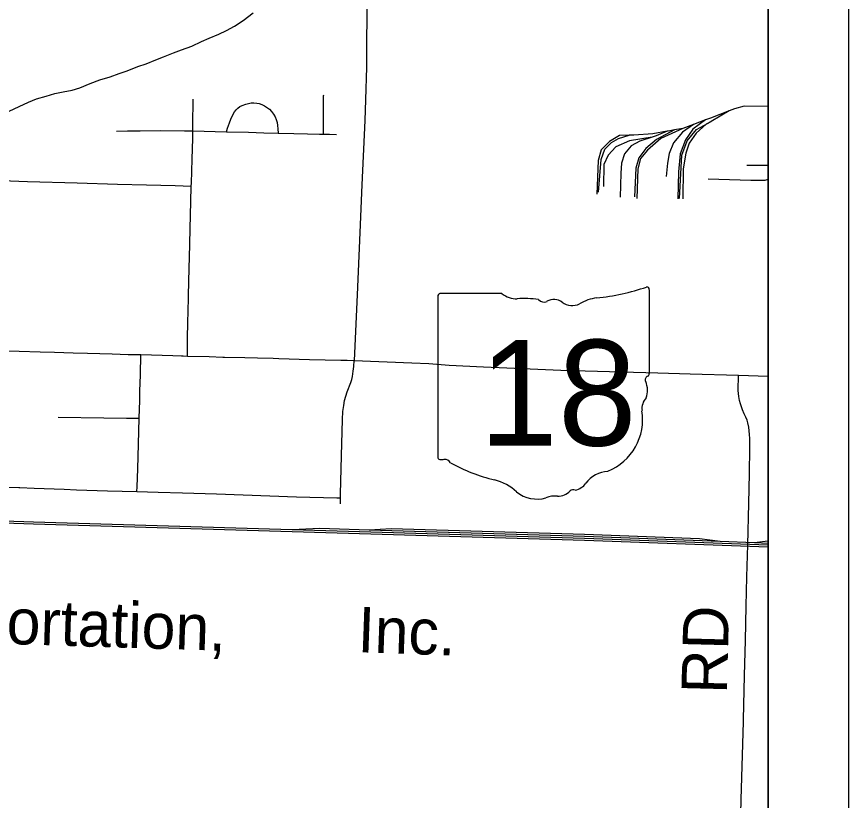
# Model space of a CAD drawing. Extents: x 0 to 34, y 0 to 22.
# Drawn here: x 29.379 to 30.417, y 17.811 to 18.788 of the extents above; entities that cross this region are included whole.
import ezdxf

# ---------------------------------------------------------------- set-up
doc = ezdxf.new("R2010")
doc.units = 0
for name, color, linetype in [('GM_X_City_Street', 7, 'Continuous'), ('GM_X_County_Road', 7, 'Continuous'), ('GM_X_County_Road_Text', 7, 'Continuous'), ('GM_X_Major_River', 7, 'Continuous'), ('GM_X_Rail_Line', 7, 'Continuous'), ('GM_X_Rail_Line_Text', 7, 'Continuous'), ('GM_X_State_Location', 7, 'Continuous'), ('GM_X_State_Route', 7, 'Continuous'), ('GM_X_State_Shield', 7, 'Continuous'), ('GM_X_Township_Road', 7, 'Continuous'), ('SH_Data', 7, 'Continuous')]:
    doc.layers.add(name, color=color, linetype=linetype)

msp = doc.modelspace()

# ---------------------------------------------------------------- linework, layer by layer
at = {"layer": 'GM_X_City_Street'}
msp.add_line((29.599, 18.6457), (29.6412, 18.6447), dxfattribs=at)
for points in [[(29.762, 18.6418), (29.762, 18.6529), (29.7621, 18.6674), (29.7622, 18.6797), (29.7623, 18.6895), (29.7624, 18.6908)], [(29.6412, 18.6447), (29.6426, 18.6492), (29.6438, 18.6527), (29.6449, 18.6557), (29.6465, 18.6603), (29.6494, 18.6665), (29.6512, 18.6697), (29.6532, 18.6722), (29.6555, 18.6742), (29.658, 18.676), (29.6608, 18.6774), (29.6654, 18.6792), (29.6684, 18.6801), (29.6721, 18.6807), (29.6751, 18.6808), (29.6789, 18.6805), (29.6819, 18.6799), (29.6854, 18.6786), (29.6887, 18.677), (29.6924, 18.6747), (29.6948, 18.6727), (29.6974, 18.67), (29.6999, 18.6665), (29.7018, 18.6633), (29.7033, 18.6599), (29.7043, 18.6563), (29.7049, 18.6526), (29.7051, 18.6483), (29.7054, 18.643)], [(29.5039, 18.6455), (29.5176, 18.6458), (29.5337, 18.646), (29.5591, 18.6462), (29.5887, 18.6459), (29.599, 18.6457)], [(29.6412, 18.6447), (29.6686, 18.6441), (29.6879, 18.6434), (29.7054, 18.643)], [(29.7054, 18.643), (29.7253, 18.6425), (29.7421, 18.6422), (29.757, 18.6419), (29.762, 18.6418)], [(29.762, 18.6418), (29.7696, 18.6416), (29.7782, 18.6414)], [(29.1792, 18.5679), (29.1884, 18.5693), (29.2024, 18.5719), (29.2172, 18.574), (29.2197, 18.5744), (29.2651, 18.5814), (29.2805, 18.5838), (29.2899, 18.5849), (29.2918, 18.5852), (29.3009, 18.5858), (29.3075, 18.5861), (29.3284, 18.5851), (29.393, 18.5828), (29.4549, 18.5811), (29.5053, 18.5794), (29.5415, 18.5786), (29.577, 18.5776), (29.5973, 18.5768)], [(29.4311, 18.2889), (29.4884, 18.2881), (29.5163, 18.2876), (29.5324, 18.2874)]]:
    msp.add_lwpolyline(points, dxfattribs=at)
at = {"layer": 'GM_X_County_Road'}
for points in [[(30.2938, 18.2543), (30.2936, 18.2623), (30.2934, 18.2673), (30.293, 18.2719), (30.2924, 18.2761), (30.2914, 18.2818), (30.2903, 18.2852), (30.2889, 18.2886), (30.2869, 18.2931), (30.2847, 18.298), (30.2834, 18.3015), (30.282, 18.3054), (30.2808, 18.3094), (30.2803, 18.3119), (30.2799, 18.3145), (30.2791, 18.3219), (30.2798, 18.3413)], [(30.2714, 17.3404), (30.2716, 17.3482), (30.2721, 17.3787), (30.273, 17.4172), (30.2745, 17.4707), (30.2772, 17.5689), (30.2807, 17.7224), (30.283, 17.812), (30.2857, 17.9089), (30.2857, 17.9102), (30.2858, 17.9114), (30.287, 17.9667), (30.2885, 18.0102), (30.2894, 18.0531), (30.2902, 18.0898), (30.2911, 18.1296), (30.2925, 18.1812), (30.2935, 18.2184), (30.2939, 18.2503), (30.2938, 18.2543)]]:
    msp.add_lwpolyline(points, dxfattribs=at)
at = {"layer": 'GM_X_Major_River'}
msp.add_lwpolyline([(29.3701, 18.6702), (29.3827, 18.6764), (29.3943, 18.6818), (29.4042, 18.6857), (29.4161, 18.6892), (29.4271, 18.6923), (29.4374, 18.6947), (29.4485, 18.6967), (29.4584, 18.6995), (29.4711, 18.7048), (29.4833, 18.7094), (29.496, 18.7133), (29.5074, 18.7172), (29.5174, 18.7207), (29.5308, 18.7261), (29.5411, 18.7296), (29.553, 18.7342), (29.5626, 18.7381), (29.5749, 18.7431), (29.5852, 18.747), (29.5978, 18.7516), (29.6101, 18.7574), (29.6197, 18.7613), (29.6316, 18.7663), (29.6412, 18.771), (29.6512, 18.7765), (29.662, 18.7834), (29.6744, 18.7929)], dxfattribs=at)
at = {"layer": 'GM_X_Rail_Line'}
for p, q in [((30.2681, 18.6708), (30.2454, 18.6577)), ((30.2383, 18.6594), (30.2235, 18.6539)), ((30.2235, 18.6539), (30.2102, 18.6489)), ((30.2102, 18.6489), (30.2, 18.647)), ((30.2901, 18.6031), (30.3167, 18.6031)), ((30.2569, 18.1341), (30.2995, 18.1325)), ((30.2995, 18.1325), (30.3161, 18.1344)), ((30.2995, 18.1325), (30.3167, 18.1318)), ((30.3161, 18.1344), (30.3167, 18.1343)), ((30.3161, 18.1344), (30.3167, 18.1344))]:
    msp.add_line(p, q, dxfattribs=at)
for points in [[(30.2681, 18.6708), (30.2446, 18.6618), (30.2383, 18.6594)], [(30.3167, 18.6762), (30.2868, 18.6766), (30.2746, 18.6733), (30.2681, 18.6708)], [(30.2383, 18.6594), (30.2227, 18.6481), (30.2135, 18.6348), (30.2069, 18.6172), (30.2048, 18.5947), (30.2038, 18.5611)], [(30.2235, 18.6539), (30.2097, 18.644), (30.1987, 18.6307), (30.1931, 18.6177), (30.1913, 18.6055), (30.1893, 18.5889)], [(30.2061, 18.5615), (30.2092, 18.6157), (30.2158, 18.6335), (30.2271, 18.6475), (30.2454, 18.6577)], [(30.2454, 18.6577), (30.2393, 18.6542), (30.2268, 18.643), (30.2181, 18.6305), (30.2141, 18.6179), (30.2105, 18.5983), (30.2102, 18.5611)], [(30.1433, 18.6403), (30.1314, 18.6399), (30.1188, 18.6327), (30.1083, 18.622), (30.1045, 18.6087), (30.103, 18.5667)], [(30.1051, 18.5692), (30.1084, 18.6101), (30.1129, 18.6228), (30.1214, 18.6315), (30.13, 18.6363), (30.1433, 18.6403)], [(30.1909, 18.6453), (30.173, 18.6422), (30.1492, 18.6405), (30.1433, 18.6403)], [(30.2, 18.647), (30.1776, 18.6351), (30.1643, 18.6238), (30.1553, 18.6123), (30.1518, 18.5994), (30.15, 18.5634)], [(30.2102, 18.6489), (30.1826, 18.6361), (30.166, 18.6218), (30.1576, 18.6113), (30.1543, 18.5985), (30.1528, 18.5615)], [(30.1909, 18.6453), (30.1771, 18.6396), (30.172, 18.6379)], [(30.2, 18.647), (30.1921, 18.6455), (30.1909, 18.6453)], [(30.172, 18.6379), (30.1438, 18.6332), (30.1267, 18.6259), (30.117, 18.6154), (30.1119, 18.6039), (30.1112, 18.5766)], [(30.172, 18.6379), (30.1568, 18.633), (30.1457, 18.6271), (30.1377, 18.617), (30.1337, 18.6054), (30.1329, 18.5929), (30.1319, 18.5633)], [(30.2419, 18.5858), (30.295, 18.5842), (30.3131, 18.5843), (30.3167, 18.5854)], [(28.9595, 18.1734), (29.4006, 18.1583), (30.0875, 18.1379), (30.3167, 18.1294)], [(28.9595, 18.1709), (29.4005, 18.1558), (30.0875, 18.1355), (30.3167, 18.1269)], [(29.7232, 18.1487), (29.7571, 18.1502), (29.8192, 18.1484)], [(29.8192, 18.1484), (29.8464, 18.1501), (30.0877, 18.1429), (30.2312, 18.1375), (30.2569, 18.1341)], [(29.8192, 18.1484), (30.0876, 18.1404), (30.2569, 18.1341)]]:
    msp.add_lwpolyline(points, dxfattribs=at)
at = {"layer": 'GM_X_State_Route'}
for p, q in [((29.6386, 18.3638), (29.6642, 18.3631)), ((29.7915, 18.3597), (29.8003, 18.3595)), ((30.2798, 18.3413), (30.3167, 18.3401))]:
    msp.add_line(p, q, dxfattribs=at)
for points in [[(29.8169, 18.925), (29.8167, 18.9141), (29.8165, 18.8688), (29.8164, 18.8327), (29.8159, 18.7525), (29.8156, 18.7251), (29.8146, 18.6847), (29.8137, 18.6586), (29.8099, 18.5785), (29.8074, 18.519), (29.804, 18.4412), (29.8003, 18.3595)], [(29.0359, 18.3804), (29.0671, 18.3795), (29.0882, 18.3789), (29.115, 18.3783), (29.1473, 18.3774), (29.2326, 18.3751), (29.2717, 18.3742), (29.2836, 18.3739), (29.2862, 18.3739), (29.3144, 18.3728), (29.3528, 18.3717), (29.3672, 18.3713), (29.3825, 18.3709), (29.4088, 18.3702), (29.4267, 18.3697), (29.4498, 18.3691), (29.4679, 18.3685), (29.4986, 18.3677), (29.5187, 18.3671), (29.5212, 18.367), (29.5344, 18.3668)], [(29.5344, 18.3668), (29.5743, 18.3656), (29.5851, 18.3653)], [(29.5851, 18.3653), (29.5871, 18.3652), (29.5925, 18.365)], [(29.5925, 18.365), (29.6197, 18.3643), (29.6366, 18.3638), (29.6386, 18.3638)], [(29.6642, 18.3631), (29.68, 18.3626), (29.6993, 18.3623), (29.7064, 18.3621)], [(29.7064, 18.3621), (29.7447, 18.3608), (29.7836, 18.3599), (29.7915, 18.3597)], [(29.8003, 18.3595), (29.8721, 18.3566), (29.8935, 18.3555), (29.9188, 18.3538), (29.9616, 18.3516), (30.0294, 18.3485), (30.058, 18.3475), (30.0733, 18.3471)], [(30.0733, 18.3471), (30.1792, 18.3439), (30.2195, 18.3428), (30.2798, 18.3413)]]:
    msp.add_lwpolyline(points, dxfattribs=at)
at = {"layer": 'GM_X_State_Shield'}
for p, q in [((29.9846, 18.4428), (29.9074, 18.4428)), ((30.1685, 18.3431), (30.1685, 18.4477)), ((29.9048, 18.4393), (29.9048, 18.2392)), ((30.1684, 18.3431), (30.1685, 18.3431))]:
    msp.add_line(p, q, dxfattribs=at)
for centre, radius, start, end in [((29.9078, 18.4398), 0.00305, 98.1301, 188.1301), ((30.003, 18.466), 0.0296, 231.6195, 271.1119), ((30.0745, 18.7156), 0.2796, 275.8445, 288.9065), ((30.1655, 18.4482), 0.00294, 351.8621, 97.738), ((30.0128, 18.3304), 0.1064, 80.4867, 94.9883), ((30.037, 18.4408), 0.00855, 219.7921, 297.1024), ((30.0495, 18.4177), 0.0178, 54.4667, 119.1411), ((30.0725, 18.4494), 0.0214, 233.8562, 294.8282), ((30.1102, 18.3817), 0.0563, 97.3462, 120.7689), ((30.1678, 18.3354), 0.00454, 107.944, 210.337), ((30.1653, 18.3427), 0.00314, 289.6038, 7.7341), ((30.1389, 18.3221), 0.0273, 340.033, 23.6496), ((30.179, 18.2993), 0.0198, 136.8065, 186.9296), ((30.0902, 18.2859), 0.0699, 292.3089, 8.9858), ((29.9078, 18.2388), 0.00308, 171.9584, 258.3066), ((29.9083, 18.2593), 0.0235, 267.339, 280.6039), ((29.9131, 18.2277), 0.00848, 29.7484, 93.2717), ((30.0202, 18.4075), 0.2019, 240.4129, 257.1985), ((30.1197, 18.183), 0.0383, 94.4031, 142.5768), ((29.96, 18.1493), 0.0632, 47.1842, 75.836), ((30.0712, 18.2198), 0.0226, 282.8732, 323.2771), ((30.0283, 18.2267), 0.0401, 230.7004, 286.2918), ((30.0544, 18.2117), 0.0214, 268.777, 315.5493), ((30.0737, 18.1923), 0.00601, 65.7517, 132.6484), ((30.0515, 18.1575), 0.0329, 85.6951, 111.2099)]:
    msp.add_arc(centre, radius, start, end, dxfattribs=at)
at = {"layer": 'GM_X_Township_Road'}
for p, q in [((29.5313, 18.255), (29.5324, 18.2874)), ((29.3682, 18.2015), (29.3823, 18.2011))]:
    msp.add_line(p, q, dxfattribs=at)
for points in [[(28.8021, 16.3696), (29.7483, 16.3505), (30.2361, 16.3375), (30.2681, 16.3359), (30.2735, 16.3357), (30.315, 16.335), (30.3167, 16.335), (30.3167, 20.9), (28.9104, 20.9)], [(29.599, 18.6457), (29.5991, 18.6487), (29.5992, 18.663), (29.5995, 18.6754), (29.5995, 18.6798), (29.5996, 18.6853)], [(29.5983, 18.6104), (29.599, 18.6363), (29.599, 18.6457)], [(29.5973, 18.5768), (29.5974, 18.5805), (29.5983, 18.6104)], [(29.5946, 18.4754), (29.5949, 18.4873), (29.5964, 18.5413), (29.5968, 18.5575), (29.5973, 18.5768)], [(29.5928, 18.4068), (29.5932, 18.4209), (29.5938, 18.4376), (29.5939, 18.4404), (29.5946, 18.4744), (29.5946, 18.4754)], [(29.5925, 18.365), (29.5926, 18.3772), (29.5927, 18.3873), (29.5928, 18.4068)], [(29.5324, 18.2874), (29.5329, 18.3095), (29.5332, 18.3211), (29.5338, 18.3416), (29.5344, 18.3668)], [(29.7834, 18.1883), (29.7835, 18.1928), (29.7845, 18.2404), (29.7858, 18.2858), (29.7864, 18.2958), (29.7873, 18.3033), (29.7884, 18.3094), (29.7898, 18.3149), (29.7916, 18.3203), (29.7963, 18.3318), (29.7976, 18.3359), (29.7984, 18.3394), (29.7993, 18.3463), (29.7999, 18.3521), (29.8003, 18.3595)], [(29.5292, 18.196), (29.5296, 18.2018), (29.5304, 18.2245), (29.5313, 18.255)], [(29.3823, 18.2011), (29.3833, 18.201), (29.4015, 18.2003), (29.4387, 18.1988), (29.4542, 18.1982), (29.4929, 18.1971), (29.5292, 18.196)], [(29.5292, 18.196), (29.5561, 18.1952), (29.5863, 18.1944), (29.6288, 18.1931), (29.7286, 18.1896), (29.7787, 18.1882), (29.7813, 18.1883), (29.7834, 18.1883)], [(29.7835, 18.1807), (29.7834, 18.187), (29.7834, 18.1883)]]:
    msp.add_lwpolyline(points, dxfattribs=at)
at = {"layer": 'SH_Data'}
for points in [[(23.4167, 21), (30.4167, 21), (30.4167, 14), (23.4167, 14)], [(23.5167, 20.9), (30.3167, 20.9), (30.3167, 14.1), (23.5167, 14.1)]]:
    msp.add_lwpolyline(points, close=True, dxfattribs=at)

# ---------------------------------------------------------------- texts
at = {"layer": 'GM_X_County_Road_Text'}
msp.add_text('RD', height=0.05682, rotation=88.5318, dxfattribs=at).set_placement((30.2652, 17.9433))
at = {"layer": 'GM_X_Rail_Line_Text'}
for s, height, rotation, p in [('Transportation,', 0.056629, 358.1792, (29.1308, 18.0135)), ('Inc.', 0.05663, 357.9797, (29.8041, 17.9957))]:
    msp.add_text(s, height=height, rotation=rotation, dxfattribs=at).set_placement(p)
at = {"layer": 'GM_X_State_Location'}
for s in ['s', 'r']:
    msp.add_text(s, height=0.000189, dxfattribs=at).set_placement((30.0337, 18.326))
msp.add_text('18', height=0.000189, rotation=0, dxfattribs=at).set_placement((29.986, 18.3122))
at = {"layer": 'GM_X_State_Shield'}
msp.add_text('18', height=0.13184, dxfattribs=at).set_placement((29.9565, 18.2533))

doc.saveas('drawing.dxf')
